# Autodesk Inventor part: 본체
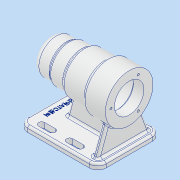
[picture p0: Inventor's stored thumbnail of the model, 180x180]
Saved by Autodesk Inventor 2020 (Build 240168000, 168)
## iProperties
Created: 2021-10
Part Number: 본체
Material: 알루미늄 6061
Document SubType Name: Modeling
Designer: user
Density: 2.7 g/cm^3
Appearance: 알루미늄 - 평지
Mass: 691.225 g
Surface Area: 699.816 cm^2
Volume: 256.009 cm^3
Author: user
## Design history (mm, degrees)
sketch "스케치1"
  geometry: L1 (0, 0)-(112, 0); L2 (0, 0)-(0, 25); L3 (0, 25)-(24, 25); L4 (24, 25)-(24, 27); L5 (24, 27)-(46, 27); L6 (46, 27)-(46, 30); L7 (46, 30)-(80, 30); L8 (80, 30)-(80, 34); L9 (80, 34)-(112, 34); L10 (6, 0)-(6, 7.5); L11 (9, 10.5)-(9, 10.5); L12 (9, 10.5)-(9, 15.7); L13 (9.3, 16)-(13, 16); L14 (13, 16)-(13, 17.2); L15 (13.3, 17.5)-(31, 17.5); L16 (31, 17.5)-(31, 20.7); L17 (31.3, 21)-(43, 21); L18 (46, 24)-(94, 24); L19 (112, 34)-(112, 21); L20 (97, 21)-(112, 21); A1 r 3 centre (9, 7.5) between (9, 10.5) and (6, 7.5); A2 r 0.3 centre (9.3, 15.7) between (9.3, 16) and (9, 15.7); A3 r 0.3 centre (13.3, 17.2) between (13.3, 17.5) and (13, 17.2); A4 r 0.3 centre (31.3, 20.7) between (31.3, 21) and (31, 20.7); A5 r 3 centre (46, 21) between (46, 24) and (43, 21); A6 r 3 centre (94, 21) between (97, 21) and (94, 24); 6 further points; 1 other entity
  constraints: 40 end point, 14 perpendicular, 12 point on circle, 10 point on line, 10 tangent, 6 centre point, 4 horizontal, 3 equal radius, 3 vertical, 2 vertical alignment, 1 collinear, 5 other
  dimensions: "d0" = 112 distance of L1.start L1.end; "d1" = 24 distance between parallel lines of L2 L4; "d2" = 46 distance between parallel lines of L6 L2; "d3" = 80 distance between parallel lines of L8 L2; "d4" = 50 diameter of L3 L1; "d5" = 54 diameter of L5 L1; "d6" = 60 diameter of L7 L1; "d7" = 68 diameter of L9 L1; "d8" = 21 diameter of L11 L1; "d9" = 32 diameter of L13 L1; "d10" = 35 diameter of L15 L1; "d11" = 18 distance between parallel lines of L16 L14; "d12" = 12 dimension on L16; "d15" = 48 diameter of L18 L1; "d16" = 42 diameter of L17 L1; "d72" = 3 radius of A1; "d73" = 0.3 radius of A2; "d74" = 3 radius of A5; "d75" = 15 distance of L20.start L19.end; "d76" = 54 distance of L20.start L17.end; "d94" = 3 distance between parallel lines of L12 L10; "d95" = 4 distance between parallel lines of L14 L12
revolve "회전1" sketch "스케치1" stored, may be unused: angle "d19" = 90 deg
node "작업 평면1"
sketch "스케치2"
  geometry: L1 (-112, 45)-(0, 45); L2 (0, 45)-(0, -45); L3 (0, -45)-(-112, -45); L4 (-112, -45)-(-112, 45); L5 (-112, 45)-(0, -45); L6 (0, 45)-(-112, -45); L7 (-112, 34)-(-112, -34) reference; 3 further points
  constraints: 12 end point, 3 midpoint, 2 parallel, 1 collinear, 1 horizontal, 1 horizontal alignment, 1 perpendicular
  dimensions: "d21" = 90 distance between parallel lines of L1 L3; "d22" = 112 distance between parallel lines of L4 L2
extrude "돌출1" join sketch "스케치2" distance "d23" = 8; taper "d24" = 0 deg
sketch "스케치3"
  geometry: L1 (112, -45)-(112, 45) reference; L2 (104, 4)-(27, 4); L3 (27, 4)-(27, -4); L4 (27, -4)-(104, -4); L5 (104, -4)-(104, 4); L6 (104, 4)-(27, -4); L7 (27, 4)-(104, -4); 4 further points
  constraints: 12 end point, 4 midpoint, 2 horizontal alignment, 2 parallel, 1 horizontal, 1 perpendicular
  dimensions: "d27" = 8 distance between parallel lines of L4 L2; "d29" = 77 distance between parallel lines of L5 L3; "d30" = 8 distance between parallel lines of L1 L5
extrude "돌출2" join sketch "스케치3" stored distance "d31" = 8; taper "d32" = 0 deg
sketch "스케치4"
  geometry: L1 (-41, -8)-(-41, 0) reference; L2 (-41, 0)-(0, 0) reference; L3 (0, 0)-(0, 28.236) reference; L4 (8, 28.236)-(8, 0) reference; L5 (8, 0)-(49, 0) reference; L6 (49, 0)-(49, -8) reference; L7 (49, -8)-(-41, -8) reference; L8 (0, 0)-(8, 0) reference; L9 (-19.409, 37.342)-(-33, 0); L10 (49, 0)-(-41, 0) reference; L11 (27.409, 37.342)-(41, 0); C1 r 21 at (4, 62) reference; A1 r 34 centre (4, 62) between (8, 28.236) and (0, 28.236) reference; A2 r 34 centre (4, 62) between (0, 28.236) and (8, 28.236) reference; 3 further points
  constraints: 4 end point, 2 point on circle, 2 point on line
  dimensions: "d33" = 8 distance from line of L1 L9.end; "d34" = 110 deg angle of L2 L9; "d35" = 110 deg angle of L5 L11; "d36" = 8 distance of L5.end L11.end
extrude "돌출3" join sketch "스케치4" distance "d37" = 8; taper "d38" = 0 deg
feature "면 기울기1" dims angle "d39" = 15 deg
sketch "스케치7"
  geometry: L1 (20, -33)-(35, -33); L2 (20, -28.5)-(35, -28.5); L3 (35, -37.5)-(20, -37.5); L4 (60, -33)-(75, -33); L5 (60, -37.5)-(75, -37.5); L6 (75, -28.5)-(60, -28.5); L7 (20, 33)-(35, 33); L8 (20, 28.5)-(35, 28.5); L9 (35, 37.5)-(20, 37.5); L10 (60, 33)-(75, 33); L11 (60, 37.5)-(75, 37.5); L12 (75, 28.5)-(60, 28.5); L13 (0, 45)-(0, -45) reference; A1 r 4.5 centre (20, -33) between (20, -28.5) and (20, -37.5); A2 r 4.5 centre (35, -33) between (35, -37.5) and (35, -28.5); A3 r 4.5 centre (60, -33) between (60, -28.5) and (60, -37.5); A4 r 4.5 centre (75, -33) between (75, -37.5) and (75, -28.5); A5 r 4.5 centre (20, 33) between (20, 37.5) and (20, 28.5); A6 r 4.5 centre (35, 33) between (35, 28.5) and (35, 37.5); A7 r 4.5 centre (60, 33) between (60, 37.5) and (60, 28.5); A8 r 4.5 centre (75, 33) between (75, 28.5) and (75, 37.5); 5 further points
  constraints: 32 end point, 16 point on circle, 16 tangent, 8 centre point, 4 horizontal, 4 midpoint, 4 parallel, 2 horizontal alignment
  dimensions: "d40" = 20 distance from line of L1.start L13; "d41" = 15 distance of L1.end L1.start; "d42" = 25 distance of L4.start L1.end; "d43" = 15 distance of L4.end L4.start; "d44" = 33 vertical distance of point (0, 0) point (27.5, -33); "d45" = 20 distance from line of L13 L7.start; "d46" = 15 distance of L7.end L7.start; "d47" = 25 distance of L10.start L7.end; "d48" = 15 distance of L10.end L10.start; "d49" = 9 distance of L3.end L2.start; "d50" = 9 distance of L5.start L6.end; "d51" = 9 distance of L8.start L9.end; "d52" = 9 distance of L12.end L11.start; "d53" = 33 vertical distance of point (0, 0) point (27.5, 33)
extrude "돌출4" cut sketch "스케치7" distance "d54" = 30; taper "d55" = 0 deg
sketch "스케치10"
  geometry: L1 (0, 45)-(0, -45) reference; L2 (0, -45)-(112, -45) reference; 2 further points
  constraints: 1 horizontal alignment, 1 other
  dimensions: "d67" = 12 distance from line of L1 point (12, 0)
feature "엠보싱1" sketch "스케치10" dims "d0" = 112, "d1" = 24, "d2" = 46, "d3" = 80, "d4" = 50, "d5" = 54, "d6" = 60, "d7" = 68, "d8" = 21, "d9" = 32, "d10" = 35, "d11" = 18, "d12" = 12, "d15" = 48, "d16" = 42, "d69" = 0.5, "d70" = 0, "d72" = 3, "d73" = 0.3, "d74" = 3, "d75" = 15, "d76" = 54, "d94" = 3, "d95" = 4
fillet "모깎기1" dims "d71" = 12
sketch "스케치13"
  geometry: 2 further points
  constraints: 1 horizontal alignment
  dimensions: "d77" = 26 distance of point (0, 0) point (-26, 0)
hole "구멍2" sketch "스케치13" at (-26, 0) diameter "d78" = 3.242; stored, may be unused: countersink angle "d82" = 90 deg, drill point angle "d84" = 118 deg; dims "d79" = 8, "d80" = 4, "d81" = 2, "d83" = 11
fillet "모깎기2" dims "d88" = 3
fillet "모깎기3" dims "d89" = 3
fillet "모깎기4" dims "d90" = 3
fillet "모깎기5" dims "d91" = 8
fillet "모깎기6" dims "d92" = 3
fillet "모깎기7" dims "d93" = 3
node "솔리드1"
pattern_circular "원형 패턴2" dims angle "d86" = 360 deg
node "절단 모서리 투영1"
feature "A9D066F2-1C7D-4E18-AEED-F7BC21143FA4" dims "d78" = 3.242, "d79" = 8, "d80" = 4, "d81" = 2, "d82" = 90 deg, "d83" = 11, "d84" = 118 deg
